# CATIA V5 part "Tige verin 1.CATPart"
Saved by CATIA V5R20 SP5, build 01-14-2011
Part number: Tige verin 1
Bounding box of the stored display mesh (mm): x -209.988 to -86.736, y -134.683 to -90.012, z -47 to -33
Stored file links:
  U:\CFAO\Thinkmotion\Tige verin 1.CATPart
  U:\CFAO\Thinkmotion\Bras Articule.CATProduct
  U:\CFAO\Thinkmotion\Squelette Tige verin 1.CATPart
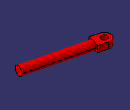
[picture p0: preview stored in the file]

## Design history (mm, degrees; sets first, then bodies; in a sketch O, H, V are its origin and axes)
Set1
  Plane1: linked copy from another document
  Point1: linked copy from another document
  Line1: linked copy from another document
Body1 (main body)
  Sketch1 on Plane1, origin (0, 0, -40), H (1, 0, 0), V (0, 1, 0)
    line L1 (-183.0225, -93.9366) -> (-197.5746, -90.2986)
    arc A1 centre (-200, -100) radius 10 from (-197.5746, -90.2986) to (-202.4254, -109.7014) ccw
    point P3 (-200, -100)
    line L2 (-202.4254, -109.7014) -> (-187.8732, -113.3395)
    line L3 (-187.8732, -113.3395) -> (-183.0225, -93.9366)
    reference projected point E1 (-200, -100) from Point1
    reference projected line E2 (-200, -100) -> (-145.5214, -113.6197) from Line1
    circle A2 centre (-200, -100) radius 5
    radius A1 = 10
    radius A2 = 5
    length L1 = 15
    tangency: A1 L1, L2 A1
    perpendicularity: L3 L1
    coincidence: P3 E1
    parallelism: L2 L1
    symmetry: L1 L2 E2
    concentricity: A2 A1
  Pad1: profile Sketch1, direction (0, 0, 1), length 5, mirrored extent
  Sketch2 on face of Pad1 from Sketch1.L3, origin (-150.1537, 37.5384, 0), H (0.2425, 0.9701, 0), V (0, 0, 1)
    circle A1 centre (-145.5214, -40) radius 7
    point P1 (-145.5214, -40)
    reference projected point E1 (-145.5214, -40) from Line1
    radius A1 = 7
    coincidence: P1 E1
  Pad2: profile Sketch2, direction (0.9701, -0.2425, 0), length 100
